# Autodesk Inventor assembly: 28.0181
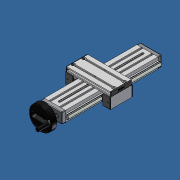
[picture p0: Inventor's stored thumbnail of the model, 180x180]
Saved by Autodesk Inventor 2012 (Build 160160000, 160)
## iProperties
Created: 2007-06
Part Number: 28.0181
Document SubType Name: Assembly
Designer: Andy Moles
Description: ADJUSTING UNIT VEW 45X90F
Author: Andy Moles
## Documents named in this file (19)
- C:\Andys Backup Data\ANDY'S INVENTOR\INVENTOR LIBRARIES\PARTS LIBRARY\READY FOR USE MODULES LG\28.0181 ADJUSTING UNIT VEW 45X90F.iam
- C:\Andys Backup Data\ANDY'S INVENTOR\INVENTOR LIBRARIES\PARTS LIBRARY\FASTENING ELEMENTS\NUTS\21.1351 M8 SQUARE NUT.ipt
- C:\Andys Backup Data\ANDY'S INVENTOR\INVENTOR LIBRARIES\PARTS LIBRARY\READY FOR USE MODULES LG\SUBCOMPONENTS\50.1264 BALL BEARING 10X30X9 6200 2RS DIN 625.ipt
- C:\Andys Backup Data\ANDY'S INVENTOR\INVENTOR LIBRARIES\PARTS LIBRARY\READY FOR USE MODULES LG\SUBCOMPONENTS\28.0201 BEARING PLATE 45X90 IDLER SIDE.ipt
- C:\Andys Backup Data\ANDY'S INVENTOR\INVENTOR LIBRARIES\PARTS LIBRARY\READY FOR USE MODULES LG\SUBCOMPONENTS\28.0200 BEARING PLATE 45X90 HANDWHEEL SIDE.ipt
- C:\Andys Backup Data\ANDY'S INVENTOR\INVENTOR LIBRARIES\PARTS LIBRARY\READY FOR USE MODULES LG\SUBCOMPONENTS\28.0204 HANDWHEEL 100mm.iam
- C:\Andys Backup Data\ANDY'S INVENTOR\INVENTOR LIBRARIES\PARTS LIBRARY\FASTENING ELEMENTS\SCREWS CAP\21.1204 M8X25.ipt
- C:\Andys Backup Data\ANDY'S INVENTOR\INVENTOR LIBRARIES\PARTS LIBRARY\READY FOR USE MODULES LG\SUBCOMPONENTS\28.0215 RAIL 45X90F.iam
- C:\Andys Backup Data\ANDY'S INVENTOR\INVENTOR LIBRARIES\PARTS LIBRARY\READY FOR USE MODULES LG\SUBCOMPONENTS\28.0221 ACME SCREW 16X4.ipt
- C:\Andys Backup Data\ANDY'S INVENTOR\INVENTOR LIBRARIES\PARTS LIBRARY\FASTENING ELEMENTS\WASHERS\21.1326 DISC SPRING 20.ipt
- C:\Andys Backup Data\ANDY'S INVENTOR\INVENTOR LIBRARIES\PARTS LIBRARY\READY FOR USE MODULES LG\SUBCOMPONENTS\28.0257 BRONZE NUT 16X4 NOTCHED.ipt
- C:\Andys Backup Data\ANDY'S INVENTOR\INVENTOR LIBRARIES\PARTS LIBRARY\READY FOR USE MODULES LG\SUBCOMPONENTS\28.0225_1 LWG 32X45-90 90X19-NSC.ipt
- C:\Andys Backup Data\ANDY'S INVENTOR\INVENTOR LIBRARIES\PARTS LIBRARY\READY FOR USE MODULES LG\SUBCOMPONENTS\28.0254 NUT SLIDE CONNECTOR 16.ipt
- C:\Andys Backup Data\ANDY'S INVENTOR\INVENTOR LIBRARIES\PARTS LIBRARY\READY FOR USE MODULES LG\SUBCOMPONENTS\28.0126 SLIDE 45X32.ipt
- C:\Andys Backup Data\ANDY'S INVENTOR\INVENTOR LIBRARIES\PARTS LIBRARY\FASTENING ELEMENTS\SCREWS CAP\21.1200 M8X16.ipt
- C:\Andys Backup Data\ANDY'S INVENTOR\INVENTOR LIBRARIES\PARTS LIBRARY\COMPONENTS LG\22.1094 SLIDE RAIL LG.iam
- C:\Andys Backup Data\ANDY'S INVENTOR\INVENTOR LIBRARIES\PARTS LIBRARY\FASTENING ELEMENTS\SCREWS CAP\21.1235 M5X16.ipt
- C:\Andys Backup Data\ANDY'S INVENTOR\INVENTOR LIBRARIES\PARTS LIBRARY\END CAPS\22.1014_1 END CAP 90X19 GRAY.ipt
- C:\Andys Backup Data\ANDY'S INVENTOR\INVENTOR LIBRARIES\PARTS LIBRARY\END CAPS\22.1003_1 END CAP 45x32 Z Gray.iam
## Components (36 placed, 18 different names)
1. 28.0215 RAIL 45X90F:1 [sub-assembly] — Mate:8, Flush:4, Flush:5, Flush:6, Flush:7, Mate:14, Flush:8, Flush:9, Mate:15, Angle:1, Angle:8, Mate:34
2. 28.0257 BRONZE NUT 16X4 NOTCHED:1 — Mate:16, Angle:1, Mate:35
3. 50.1264 10X30X9 6200 2RS DIN 625 BALL BEARING:1 — Mate:10, Insert:10
4. 50.1264 10X30X9 6200 2RS DIN 625 BALL BEARING:2 — Mate:11, Insert:11, Insert:14
5. 28.0201 BEARING PLATE 45X90 IDLER SIDE:1 — Insert:6, Insert:7, Mate:8, Mate:11, Flush:4, Flush:5, Insert:11
6. 28.0200 BEARING PLATE 45X90 HANDWHEEL SIDE:1 — Insert:5, Insert:8, Insert:9, Mate:10, Flush:6, Flush:7, Insert:10, Mate:15
7. 28.0204 HANDWHEEL 100mm:1 [sub-assembly] — Insert:5
8. 21.1204  M8 x 25:1 — Insert:7
9. 21.1204  M8 x 25:2 — Insert:6
10. 21.1204  M8 x 25:3 — Insert:8
11. 21.1204  M8 x 25:4 — Insert:9
12. 28.0221 ACME SCREW 16X4:1 — Insert:12, Insert:13, Mate:16
13. 21.1326 DISC SPRING 20:1 — Insert:12
14. 21.1326 DISC SPRING 20:2 — Insert:13, Insert:14
15. 28.0225_1 LWG 32X45-90 90X19-NSC:1 — Mate:17, Flush:10, Mate:18, Flush:11, Insert:15, Insert:16, Insert:17, Insert:18, Mate:19, Mate:20, Mate:21, Mate:22, Angle:2, Angle:3, Angle:4, Angle:5, Flush:12, Flush:13, Mate:32, Mate:33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
16. 28.0254 NUT SLIDE CONNECTOR 16:1 — Mate:32, Mate:33, Angle:7, Flush:16, Mate:35
17. 28.0126 SLIDE 45X32:1 — Mate:17, Flush:10, Flush:12, Mate:27, Flush:14, Mate:28, Angle:7, Insert:23, Insert:24, Angle:10, Angle:11
18. 28.0126 SLIDE 45X32:2 — Mate:18, Flush:11, Flush:13, Mate:29, Flush:15, Mate:30, Insert:21, Insert:22, Angle:12
19. 21.1200 M8 x 16:1 — Insert:15, Mate:25
20. 21.1200 M8 x 16:2 — Insert:16, Mate:26
21. 21.1200 M8 x 16:3 — Insert:18, Mate:24
22. 21.1200 M8 x 16:4 — Insert:17, Mate:23
23. 21.1351 M8 SQUARE NUT:1 — Mate:21, Mate:23, Angle:5
24. 21.1351 M8 SQUARE NUT:2 — Mate:22, Mate:24, Angle:4
25. 21.1351 M8 SQUARE NUT:3 — Mate:20, Mate:25, Angle:3
26. 21.1351 M8 SQUARE NUT:4 — Mate:19, Mate:26, Angle:2
27. 22.1094 SLIDE RAIL LG:1 [sub-assembly] — Mate:29, Flush:15, Mate:30, Mate:34
28. 22.1094 SLIDE RAIL LG:2 [sub-assembly] — Mate:27, Flush:14, Mate:28
29. 21.1235  M5 x 16:1 — Insert:20
30. 21.1235  M5 x 16:2 — Insert:19
31. 22.1014_1 END CAP 90X19 GRAY:1 — Mate:36, Angle:9, Flush:17, Flush:18
32. 22.1014_1 END CAP 90X19 GRAY:2 — Mate:37, Flush:19, Flush:20
33. 22.1003\1 END CAP 45x32 Z Gray:1 [sub-assembly] — Insert:21
34. 22.1003\1 END CAP 45x32 Z Gray:2 [sub-assembly] — Insert:22, Angle:12
35. 22.1003\1 END CAP 45x32 Z Gray:3 [sub-assembly] — Insert:23, Angle:11
36. 22.1003\1 END CAP 45x32 Z Gray:4 [sub-assembly] — Insert:24, Angle:10
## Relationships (74: Mate 26, Insert 20, Flush 17, Angle 11)
- Insert:5: 28.0200 BEARING PLATE 45X90 HANDWHEEL SIDE:1 ↔ 28.0204 HANDWHEEL 100mm:1
- Insert:6: 28.0201 BEARING PLATE 45X90 IDLER SIDE:1 ↔ 21.1204  M8 x 25:2
- Insert:7: 28.0201 BEARING PLATE 45X90 IDLER SIDE:1 ↔ 21.1204  M8 x 25:1
- Insert:8: 28.0200 BEARING PLATE 45X90 HANDWHEEL SIDE:1 ↔ 21.1204  M8 x 25:3
- Insert:9: 28.0200 BEARING PLATE 45X90 HANDWHEEL SIDE:1 ↔ 21.1204  M8 x 25:4
- Mate:8: 28.0215 RAIL 45X90F:1 ↔ 28.0201 BEARING PLATE 45X90 IDLER SIDE:1
- Mate:10: 50.1264 10X30X9 6200 2RS DIN 625 BALL BEARING:1 ↔ 28.0200 BEARING PLATE 45X90 HANDWHEEL SIDE:1
- Mate:11: 50.1264 10X30X9 6200 2RS DIN 625 BALL BEARING:2 ↔ 28.0201 BEARING PLATE 45X90 IDLER SIDE:1
- Flush:4: 28.0215 RAIL 45X90F:1 ↔ 28.0201 BEARING PLATE 45X90 IDLER SIDE:1
- Flush:5: 28.0215 RAIL 45X90F:1 ↔ 28.0201 BEARING PLATE 45X90 IDLER SIDE:1
- Flush:6: 28.0215 RAIL 45X90F:1 ↔ 28.0200 BEARING PLATE 45X90 HANDWHEEL SIDE:1
- Flush:7: 28.0215 RAIL 45X90F:1 ↔ 28.0200 BEARING PLATE 45X90 HANDWHEEL SIDE:1
- Mate:14: 28.0215 RAIL 45X90F:1
- Flush:8: 28.0215 RAIL 45X90F:1
- Flush:9: 28.0215 RAIL 45X90F:1
- Insert:10: 50.1264 10X30X9 6200 2RS DIN 625 BALL BEARING:1 ↔ 28.0200 BEARING PLATE 45X90 HANDWHEEL SIDE:1
- Mate:15: 28.0215 RAIL 45X90F:1 ↔ 28.0200 BEARING PLATE 45X90 HANDWHEEL SIDE:1
- Insert:11: 50.1264 10X30X9 6200 2RS DIN 625 BALL BEARING:2 ↔ 28.0201 BEARING PLATE 45X90 IDLER SIDE:1
- Insert:12: 28.0221 ACME SCREW 16X4:1 ↔ 21.1326 DISC SPRING 20:1
- Insert:13: 28.0221 ACME SCREW 16X4:1 ↔ 21.1326 DISC SPRING 20:2
- Insert:14: 50.1264 10X30X9 6200 2RS DIN 625 BALL BEARING:2 ↔ 21.1326 DISC SPRING 20:2
- Mate:16: 28.0257 BRONZE NUT 16X4 NOTCHED:1 ↔ 28.0221 ACME SCREW 16X4:1
- Angle:1: 28.0215 RAIL 45X90F:1 ↔ 28.0257 BRONZE NUT 16X4 NOTCHED:1
- Mate:17: 28.0225_1 LWG 32X45-90 90X19-NSC:1 ↔ 28.0126 SLIDE 45X32:1
- Flush:10: 28.0225_1 LWG 32X45-90 90X19-NSC:1 ↔ 28.0126 SLIDE 45X32:1
- Mate:18: 28.0225_1 LWG 32X45-90 90X19-NSC:1 ↔ 28.0126 SLIDE 45X32:2
- Flush:11: 28.0225_1 LWG 32X45-90 90X19-NSC:1 ↔ 28.0126 SLIDE 45X32:2
- Insert:15: 28.0225_1 LWG 32X45-90 90X19-NSC:1 ↔ 21.1200 M8 x 16:1
- Insert:16: 28.0225_1 LWG 32X45-90 90X19-NSC:1 ↔ 21.1200 M8 x 16:2
- Insert:17: 28.0225_1 LWG 32X45-90 90X19-NSC:1 ↔ 21.1200 M8 x 16:4
- Insert:18: 28.0225_1 LWG 32X45-90 90X19-NSC:1 ↔ 21.1200 M8 x 16:3
- Mate:19: 28.0225_1 LWG 32X45-90 90X19-NSC:1 ↔ 21.1351 M8 SQUARE NUT:4
- Mate:20: 28.0225_1 LWG 32X45-90 90X19-NSC:1 ↔ 21.1351 M8 SQUARE NUT:3
- Mate:21: 28.0225_1 LWG 32X45-90 90X19-NSC:1 ↔ 21.1351 M8 SQUARE NUT:1
- Mate:22: 28.0225_1 LWG 32X45-90 90X19-NSC:1 ↔ 21.1351 M8 SQUARE NUT:2
- Mate:23: 21.1200 M8 x 16:4 ↔ 21.1351 M8 SQUARE NUT:1
- Mate:24: 21.1200 M8 x 16:3 ↔ 21.1351 M8 SQUARE NUT:2
- Mate:25: 21.1200 M8 x 16:1 ↔ 21.1351 M8 SQUARE NUT:3
- Mate:26: 21.1200 M8 x 16:2 ↔ 21.1351 M8 SQUARE NUT:4
- Angle:2: 28.0225_1 LWG 32X45-90 90X19-NSC:1 ↔ 21.1351 M8 SQUARE NUT:4
- Angle:3: 28.0225_1 LWG 32X45-90 90X19-NSC:1 ↔ 21.1351 M8 SQUARE NUT:3
- Angle:4: 28.0225_1 LWG 32X45-90 90X19-NSC:1 ↔ 21.1351 M8 SQUARE NUT:2
- Angle:5: 28.0225_1 LWG 32X45-90 90X19-NSC:1 ↔ 21.1351 M8 SQUARE NUT:1
- Flush:12: 28.0225_1 LWG 32X45-90 90X19-NSC:1 ↔ 28.0126 SLIDE 45X32:1
- Flush:13: 28.0225_1 LWG 32X45-90 90X19-NSC:1 ↔ 28.0126 SLIDE 45X32:2
- Mate:27: 28.0126 SLIDE 45X32:1 ↔ 22.1094 SLIDE RAIL LG:2
- Flush:14: 28.0126 SLIDE 45X32:1 ↔ 22.1094 SLIDE RAIL LG:2
- Mate:28: 28.0126 SLIDE 45X32:1 ↔ 22.1094 SLIDE RAIL LG:2
- Mate:29: 28.0126 SLIDE 45X32:2 ↔ 22.1094 SLIDE RAIL LG:1
- Flush:15: 28.0126 SLIDE 45X32:2 ↔ 22.1094 SLIDE RAIL LG:1
- Mate:30: 28.0126 SLIDE 45X32:2 ↔ 22.1094 SLIDE RAIL LG:1
- Mate:32: 28.0225_1 LWG 32X45-90 90X19-NSC:1 ↔ 28.0254 NUT SLIDE CONNECTOR 16:1
- Mate:33: 28.0225_1 LWG 32X45-90 90X19-NSC:1 ↔ 28.0254 NUT SLIDE CONNECTOR 16:1
- Angle:7: 28.0254 NUT SLIDE CONNECTOR 16:1 ↔ 28.0126 SLIDE 45X32:1
- Flush:16: 28.0225_1 LWG 32X45-90 90X19-NSC:1 ↔ 28.0254 NUT SLIDE CONNECTOR 16:1
- Angle:8: 28.0215 RAIL 45X90F:1 ↔ 28.0225_1 LWG 32X45-90 90X19-NSC:1
- Mate:34: 28.0215 RAIL 45X90F:1 ↔ 22.1094 SLIDE RAIL LG:1
- Mate:35: 28.0257 BRONZE NUT 16X4 NOTCHED:1 ↔ 28.0254 NUT SLIDE CONNECTOR 16:1
- Insert:19: 28.0225_1 LWG 32X45-90 90X19-NSC:1 ↔ 21.1235  M5 x 16:2
- Insert:20: 28.0225_1 LWG 32X45-90 90X19-NSC:1 ↔ 21.1235  M5 x 16:1
- Mate:36: 28.0225_1 LWG 32X45-90 90X19-NSC:1 ↔ 22.1014_1 END CAP 90X19 GRAY:1
- Angle:9: 28.0225_1 LWG 32X45-90 90X19-NSC:1 ↔ 22.1014_1 END CAP 90X19 GRAY:1
- Flush:17: 28.0225_1 LWG 32X45-90 90X19-NSC:1 ↔ 22.1014_1 END CAP 90X19 GRAY:1
- Flush:18: 28.0225_1 LWG 32X45-90 90X19-NSC:1 ↔ 22.1014_1 END CAP 90X19 GRAY:1
- Mate:37: 28.0225_1 LWG 32X45-90 90X19-NSC:1 ↔ 22.1014_1 END CAP 90X19 GRAY:2
- Flush:19: 28.0225_1 LWG 32X45-90 90X19-NSC:1 ↔ 22.1014_1 END CAP 90X19 GRAY:2
- Flush:20: 28.0225_1 LWG 32X45-90 90X19-NSC:1 ↔ 22.1014_1 END CAP 90X19 GRAY:2
- Insert:21: 28.0126 SLIDE 45X32:2 ↔ 22.1003\1 END CAP 45x32 Z Gray:1
- Insert:22: 28.0126 SLIDE 45X32:2 ↔ 22.1003\1 END CAP 45x32 Z Gray:2
- Insert:23: 28.0126 SLIDE 45X32:1 ↔ 22.1003\1 END CAP 45x32 Z Gray:3
- Insert:24: 28.0126 SLIDE 45X32:1 ↔ 22.1003\1 END CAP 45x32 Z Gray:4
- Angle:10: 28.0126 SLIDE 45X32:1 ↔ 22.1003\1 END CAP 45x32 Z Gray:4
- Angle:11: 28.0126 SLIDE 45X32:1 ↔ 22.1003\1 END CAP 45x32 Z Gray:3
- Angle:12: 28.0126 SLIDE 45X32:2 ↔ 22.1003\1 END CAP 45x32 Z Gray:2
